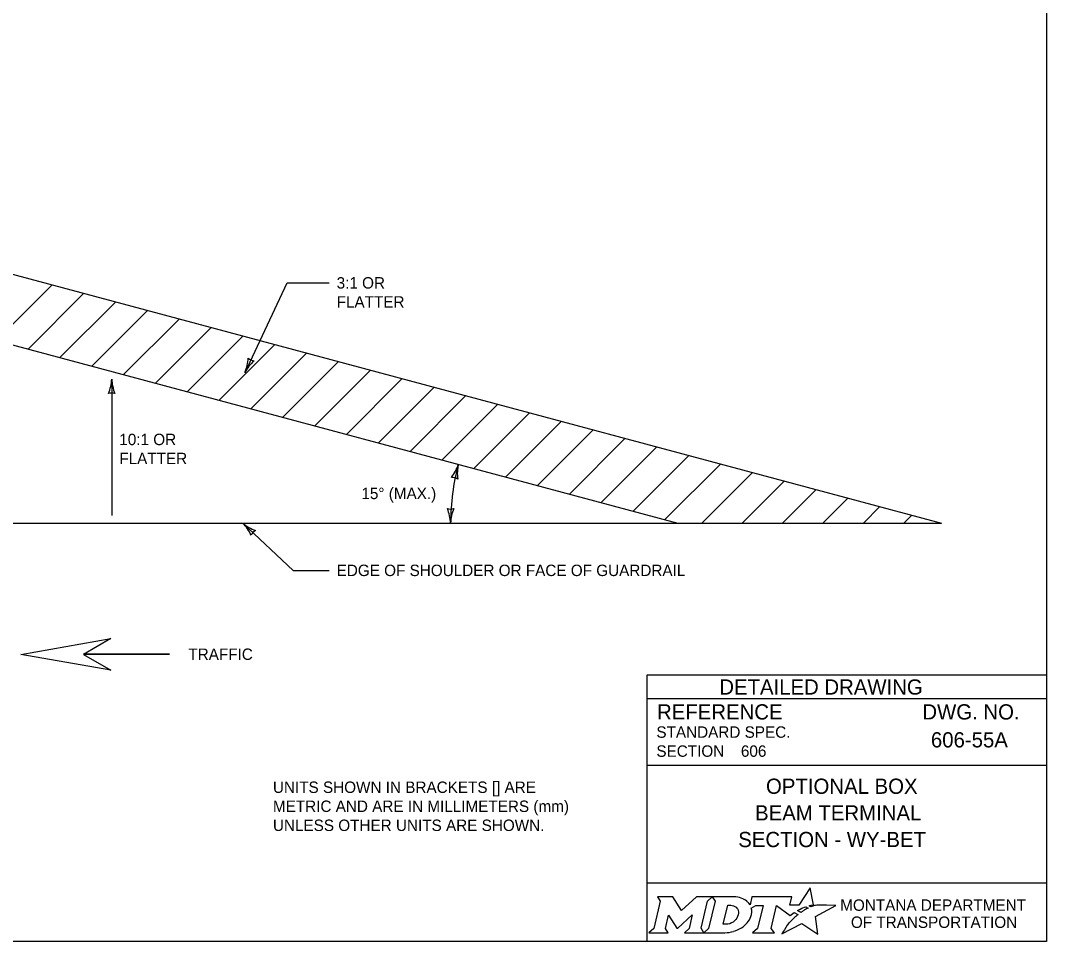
# Model space of a CAD drawing. Extents: x 49991.4 to 50021, y 49987.6 to 50011.4.
# Drawn here: x 50011.36 to 50016.75, y 49987.8 to 49992.64 of the extents above; entities that cross this region are included whole.
import ezdxf

# ---------------------------------------------------------------- set-up
doc = ezdxf.new("R2010")
doc.units = 0
for name, color, linetype in [('Default', 7, 'Continuous'), ('Level 1', 7, 'Continuous'), ('Level 2', 7, 'Continuous'), ('Level 3', 7, 'Continuous'), ('Level 5', 7, 'Continuous')]:
    doc.layers.add(name, color=color, linetype=linetype)

msp = doc.modelspace()

# ---------------------------------------------------------------- linework, layer by layer
at = {"layer": 'Default'}
for points in [[(50015.5126, 49987.9811), (50015.5023, 49987.9867), (50015.5139, 49987.9895), (50015.5255, 49987.9915), (50015.5081, 49988.0816), (50015.4486, 49987.9903), (50015.4013, 49987.9896), (50015.4116, 49988.0337), (50015.2024, 49988.0338), (50015.1923, 49987.9913), (50015.1865, 49987.9996)], [(50014.7056, 49988.0338), (50014.7197, 49988.0104), (50014.6862, 49987.8671), (50014.6605, 49987.8446), (50014.7621, 49987.8446), (50014.7486, 49987.8674), (50014.7648, 49987.9375), (50014.8085, 49987.8685), (50014.8138, 49987.8685), (50014.8889, 49987.938), (50014.8725, 49987.8669), (50014.8478, 49987.8449), (50014.9494, 49987.8449), (50014.9356, 49987.8682), (50014.9688, 49988.0106)], [(50014.9688, 49988.0106), (50014.9941, 49988.0338), (50014.9117, 49988.0338), (50014.8321, 49987.9608), (50014.7876, 49988.0335), (50014.7056, 49988.0338)], [(50015.1077, 49988.0338), (50014.9941, 49988.0338), (50015.0088, 49988.0109), (50014.9749, 49987.8671), (50014.9494, 49987.8449), (50015.06, 49987.8449)], [(50015.1317, 49987.9471), (50015.1305, 49987.939), (50015.1273, 49987.9297), (50015.1231, 49987.9215), (50015.1175, 49987.914), (50015.111, 49987.9071), (50015.1031, 49987.9008), (50015.0948, 49987.8961), (50015.0857, 49987.8922), (50015.0766, 49987.8899), (50015.0674, 49987.889), (50015.0515, 49987.889), (50015.0751, 49987.989), (50015.0911, 49987.989), (50015.0987, 49987.9884), (50015.1063, 49987.9865), (50015.1129, 49987.9835), (50015.119, 49987.9793), (50015.1238, 49987.9743), (50015.1275, 49987.9683), (50015.1302, 49987.9621), (50015.1318, 49987.9547), (50015.1318, 49987.9517), (50015.1317, 49987.9471)], [(50015.1991, 49987.9747), (50015.2237, 49987.9878), (50015.2606, 49987.9878), (50015.232, 49987.8673), (50015.2045, 49987.8446), (50015.3207, 49987.8446), (50015.3037, 49987.8675), (50015.3319, 49987.9877), (50015.4032, 49987.936), (50015.4243, 49987.9511), (50015.444, 49987.9402)], [(50015.3882, 49987.8843), (50015.3729, 49987.8599), (50015.3682, 49987.8524), (50015.3624, 49987.8438), (50015.3601, 49987.8395), (50015.4654, 49987.8926), (50015.5493, 49987.8375), (50015.5362, 49987.9302), (50015.6431, 49987.9886), (50015.5938, 49987.9894), (50015.5637, 49987.9898), (50015.5429, 49987.9901), (50015.5361, 49987.9886), (50015.5312, 49987.9874), (50015.5228, 49987.9851), (50015.5126, 49987.9811)], [(50015.4622, 49987.9535), (50015.4598, 49987.9518), (50015.4415, 49987.9614), (50015.4518, 49987.9671), (50015.4559, 49987.9693), (50015.4645, 49987.9733), (50015.4702, 49987.9759), (50015.4781, 49987.9789), (50015.4854, 49987.9816), (50015.4972, 49987.9742), (50015.4932, 49987.9721), (50015.4886, 49987.9696), (50015.4844, 49987.9674), (50015.4794, 49987.9645), (50015.4775, 49987.9634), (50015.4748, 49987.9618), (50015.4723, 49987.9604), (50015.47, 49987.9588), (50015.4674, 49987.957), (50015.4647, 49987.9552), (50015.4622, 49987.9535)], [(50015.1057, 49987.8522), (50015.1141, 49987.8548), (50015.1271, 49987.8602), (50015.1475, 49987.8712)], [(50015.4021, 49987.9004), (50015.4021, 49987.9004)]]:
    msp.add_lwpolyline(points, dxfattribs=at)
for centre, radius, start, end in [((50015.1308, 49987.9554), 0.0709, 339.5329, 15.8582), ((50015.0868, 49987.9727), 0.1183, 300.9103, 339.1383)]:
    msp.add_arc(centre, radius, start, end, dxfattribs=at)
for centre, major_axis, ratio, start_param, end_param in [((50015.1056, 49987.9864), (0.0834, -0.0037), 0.568097, 0.61298, 1.570796), ((50015.1612, 49987.9937), (0.0361, -0.0295), 0.469099, 1.225588, 1.570796), ((50015.4119, 49987.9106), (-0.0098, -0.0102), 0.016458, 3.141593, 6.279097), ((50015.4329, 49987.9305), (-0.0112, -0.0097), 0.021651, 3.157348, 6.283185), ((50015.3952, 49987.8923), (-0.00694, -0.00806), 0.008222, 0, 3.137361), ((50015.0603, 49987.9932), (0, 0.1484), 0.987302, 3.139398, 3.456847)]:
    msp.add_ellipse(centre, major_axis=major_axis, ratio=ratio, start_param=start_param, end_param=end_param, dxfattribs=at)
at = {"layer": 'Level 1'}
for p, q in [((50010.6629, 49991.481), (50016.1992, 49989.9977)), ((50011.2318, 49990.9571), (50011.5248, 49991.2501)), ((50011.399, 49990.9123), (50011.692, 49991.2053)), ((50011.5664, 49990.8675), (50011.8593, 49991.1604)), ((50010.6629, 49991.1095), (50014.8128, 49989.9977)), ((50011.7337, 49990.8226), (50012.0267, 49991.1156)), ((50011.9009, 49990.7778), (50012.1939, 49991.0708)), ((50012.0683, 49990.733), (50012.3613, 49991.026)), ((50012.2356, 49990.6881), (50012.5286, 49990.9811)), ((50012.4028, 49990.6433), (50012.6958, 49990.9363)), ((50012.5702, 49990.5985), (50012.8632, 49990.8915)), ((50012.7376, 49990.5537), (50013.0305, 49990.8466)), ((50012.9048, 49990.5089), (50013.1978, 49990.8019)), ((50013.0721, 49990.464), (50013.3651, 49990.757)), ((50013.2394, 49990.4192), (50013.5324, 49990.7122)), ((50013.4067, 49990.3744), (50013.6997, 49990.6674)), ((50013.5741, 49990.3296), (50013.867, 49990.6225)), ((50013.7413, 49990.2848), (50014.0342, 49990.5777)), ((50013.9086, 49990.2399), (50014.2016, 49990.5329)), ((50014.076, 49990.1951), (50014.369, 49990.4881)), ((50014.2432, 49990.1503), (50014.5362, 49990.4433)), ((50014.4106, 49990.1055), (50014.7035, 49990.3984)), ((50014.5779, 49990.0606), (50014.8709, 49990.3536)), ((50014.7451, 49990.0158), (50015.0381, 49990.3088)), ((50014.9392, 49989.9977), (50015.2054, 49990.2639)), ((50015.1514, 49989.9977), (50015.3728, 49990.2191)), ((50015.3634, 49989.9977), (50015.54, 49990.1743)), ((50015.5756, 49989.9977), (50015.7074, 49990.1295)), ((50015.7878, 49989.9977), (50015.8747, 49990.0846)), ((50015.9998, 49989.9977), (50016.0419, 49990.0398)), ((50012.1412, 49989.3083), (50011.6893, 49989.3083)), ((50012.1412, 49989.3078), (50011.6893, 49989.3078))]:
    msp.add_line(p, q, dxfattribs=at)
for points in [[(49999.3835, 49998.9992), (50016.7501, 49998.9992), (50016.7501, 49987.7988), (49999.3835, 49987.7988)], [(50011.8338, 49989.2245), (50011.3609, 49989.3078), (50011.8338, 49989.3916), (50011.6895, 49989.3078)]]:
    msp.add_lwpolyline(points, close=True, dxfattribs=at)
msp.add_lwpolyline([(50010.5963, 49989.9977), (50016.1992, 49989.9977)], dxfattribs=at)
at = {"layer": 'Level 3'}
for p, q in [((50012.5387, 49990.7888), (50012.7595, 49991.26)), ((50012.7595, 49991.26), (50012.9802, 49991.26)), ((50011.8382, 49990.7546), (50011.8382, 49990.0377)), ((50012.5269, 49989.9977), (50012.7924, 49989.7491)), ((50012.7924, 49989.7491), (50012.9802, 49989.7491))]:
    msp.add_line(p, q, dxfattribs=at)
for centre, radius, start, end in [((50012.323, 49990.8774), 0.233, 337.72, 356.9698), ((50012.7358, 49990.6865), 0.2223, 132.3487, 152.5322), ((50012.593, 49990.9052), 0.0548, 227.0315, 262.7538), ((50011.6161, 49990.7638), 0.2223, 337.456, 357.6395), ((50012.0709, 49990.7661), 0.233, 182.8273, 202.0772), ((50011.8382, 49990.6264), 0.0548, 72.1388, 107.8612), ((50014.8128, 49989.9977), 1.1938, 165.0021, 180), ((50013.4474, 49990.373), 0.2223, 322.4581, 342.6416), ((50013.8874, 49990.2575), 0.233, 167.8294, 187.0793), ((50013.6264, 49990.1828), 0.0548, 57.1409, 92.8633), ((50013.619, 49990.1259), 0.0548, 252.1388, 287.8612), ((50013.3862, 49989.9862), 0.233, 2.8273, 22.0772), ((50013.8411, 49989.9885), 0.2223, 157.456, 177.6395), ((50012.3684, 49989.8418), 0.2223, 24.3388, 44.5223), ((50012.6776, 49990.1754), 0.233, 229.7101, 248.96), ((50012.6205, 49989.9101), 0.0548, 119.0216, 154.744)]:
    msp.add_arc(centre, radius, start, end, dxfattribs=at)
at = {"layer": 'Level 5'}
for p, q in [((50016.7501, 49989.1988), (50014.6501, 49989.1988)), ((50014.6501, 49989.1988), (50014.6501, 49987.7988)), ((50016.7501, 49989.0738), (50014.6501, 49989.0738)), ((50016.3862, 49988.8587), (50016.3862, 49988.8587)), ((50015.1444, 49988.7993), (50015.1444, 49988.7993)), ((50016.7501, 49988.7238), (50014.6501, 49988.7238)), ((50015.7001, 49988.4747), (50015.7001, 49988.4747)), ((50016.7501, 49988.1057), (50014.6501, 49988.1057))]:
    msp.add_line(p, q, dxfattribs=at)

# ---------------------------------------------------------------- texts
at = {"layer": 'Default'}
for s, p in [('MONTANA DEPARTMENT', (50015.6663, 49987.96)), ('OF TRANSPORTATION', (50015.7225, 49987.87))]:
    msp.add_text(s, height=0.06, dxfattribs=at).set_placement(p)
at = {"layer": 'Level 2'}
for s, height, p in [('3:1 OR', 0.06, (50013.0202, 49991.23)), ('FLATTER', 0.06, (50013.0202, 49991.13)), ('10:1 OR', 0.06, (50011.8782, 49990.4073)), ('FLATTER', 0.06, (50011.8782, 49990.3073)), ('15° (MAX.)', 0.06, (50013.1503, 49990.1235)), ('EDGE OF SHOULDER OR FACE OF GUARDRAIL', 0.06, (50013.0202, 49989.7191)), ('TRAFFIC', 0.06, (50012.2412, 49989.2783)), ('606-55A', 0.08, (50016.1428, 49988.8187)), ('606', 0.06, (50015.1444, 49988.7693)), ('UNITS SHOWN IN BRACKETS [] ARE ', 0.06, (50012.6854, 49988.5794)), ('OPTIONAL BOX', 0.08, (50015.2762, 49988.5747)), ('METRIC AND ARE IN MILLIMETERS (mm) ', 0.06, (50012.6854, 49988.4794)), ('BEAM TERMINAL', 0.08, (50015.2189, 49988.4347)), ('UNLESS OTHER UNITS ARE SHOWN.', 0.06, (50012.6854, 49988.3794)), ('SECTION - WY-BET', 0.08, (50015.1304, 49988.2947))]:
    msp.add_text(s, height=height, dxfattribs=at).set_placement(p)
at = {"layer": 'Level 5'}
for s, height, p in [('DETAILED DRAWING', 0.0799, (50015.0311, 49989.0963)), ('REFERENCE', 0.08, (50014.7037, 49988.9654)), ('DWG. NO.', 0.08, (50016.0979, 49988.9654)), ('STANDARD SPEC.', 0.06, (50014.7004, 49988.8694)), ('SECTION', 0.06, (50014.7004, 49988.7694))]:
    msp.add_text(s, height=height, dxfattribs=at).set_placement(p)

doc.saveas('drawing.dxf')
